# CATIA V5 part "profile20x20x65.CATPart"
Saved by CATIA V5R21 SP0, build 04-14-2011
Part number: 65
Bounding box of the stored display mesh (mm): x -24.289 to -4.289, y -1.335 to 18.665, z 0 to 65
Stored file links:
  C:\Users\2027.DESARCY-LEMIE30\Desktop\V14(17.02.2023)\profile20x20x65.CATPart
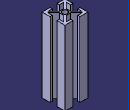
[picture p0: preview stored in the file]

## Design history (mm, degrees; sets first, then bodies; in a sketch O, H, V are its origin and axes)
Body1 (main body)
  Sketch1 on xy-plane, origin (0, 0, 0), H (1, 0, 0), V (0, 1, 0)
    point P1 (-17.2892, 11.6647)
    line L1 (-16.2892, 11.6647) -> (-12.2892, 11.6647)
    point P2 (-11.2892, 11.6647)
    line L2 (-11.2892, 10.6647) -> (-11.2892, 6.6647)
    point P3 (-11.2892, 5.6647)
    line L3 (-12.2892, 5.6647) -> (-16.2892, 5.6647)
    point P4 (-17.2892, 5.6647)
    line L4 (-17.2892, 6.6647) -> (-17.2892, 10.6647)
    point P5 (-24.2892, 18.6647)
    point P6 (-4.2892, 18.6647)
    point P7 (-4.2892, -1.3353)
    line L5 (-11.1892, 18.6647) -> (-11.1892, 16.6647)
    point P8 (-11.1892, 18.6647)
    point P10 (-11.1892, 18.6647)
    point P11 (-17.3892, 18.6647)
    line L6 (-17.3892, 18.6647) -> (-17.3892, 16.6647)
    point P12 (-17.3892, 18.6647)
    line L7 (-11.1892, 18.6647) -> (-4.2892, 18.6647)
    point P14 (-11.1892, 18.6647)
    point P15 (-4.2892, 18.6647)
    point P16 (-11.1892, -1.3353)
    point P17 (-17.3892, -1.3353)
    line L8 (-17.3892, -1.3353) -> (-17.3892, 0.6647)
    point P18 (-17.3892, -1.3353)
    line L9 (-11.1892, -1.3353) -> (-11.1892, 0.6647)
    point P20 (-11.1892, -1.3353)
    line L10 (-24.2892, -1.3353) -> (-17.3892, -1.3353)
    point P22 (-24.2892, -1.3353)
    point P23 (-17.3892, -1.3353)
    line L11 (-11.1892, -1.3353) -> (-4.2892, -1.3353)
    point P24 (-11.1892, -1.3353)
    point P25 (-4.2892, -1.3353)
    line L12 (-24.2892, 18.6647) -> (-17.3892, 18.6647)
    point P26 (-24.2892, 18.6647)
    point P27 (-17.3892, 18.6647)
    point P28 (-4.2892, 5.5647)
    point P29 (-4.2892, 11.7647)
    line L13 (-6.2892, 11.7647) -> (-4.2892, 11.7647)
    point P31 (-4.2892, 11.7647)
    line L14 (-4.2892, 5.5647) -> (-6.2892, 5.5647)
    point P32 (-4.2892, 5.5647)
    point P34 (-24.2892, 5.5647)
    point P35 (-24.2892, 11.7647)
    line L15 (-24.2892, 11.7647) -> (-22.2892, 11.7647)
    point P36 (-24.2892, 11.7647)
    line L16 (-24.2892, 5.5647) -> (-22.2892, 5.5647)
    point P38 (-24.2892, 5.5647)
    line L17 (-4.2892, 18.6647) -> (-4.2892, 11.7647)
    point P40 (-4.2892, 18.6647)
    point P41 (-4.2892, 11.7647)
    line L18 (-24.2892, 18.6647) -> (-24.2892, 11.7647)
    point P42 (-24.2892, 18.6647)
    point P43 (-24.2892, 11.7647)
    line L19 (-24.2892, -1.3353) -> (-24.2892, 5.5647)
    point P44 (-24.2892, -1.3353)
    point P45 (-24.2892, 5.5647)
    line L20 (-4.2892, -1.3353) -> (-4.2892, 5.5647)
    point P46 (-4.2892, -1.3353)
    point P47 (-4.2892, 5.5647)
    line L21 (-22.2892, 5.5647) -> (-22.2892, 1.6647)
    line L22 (-21.2892, 0.6647) -> (-17.3892, 0.6647)
    line L23 (-6.2892, 5.5647) -> (-6.2892, 1.6647)
    line L24 (-11.1892, 0.6647) -> (-7.2892, 0.6647)
    line L25 (-11.1892, 16.6647) -> (-7.2892, 16.6647)
    line L26 (-6.2892, 15.6647) -> (-6.2892, 11.7647)
    line L27 (-17.3892, 16.6647) -> (-21.2892, 16.6647)
    line L28 (-22.2892, 15.6647) -> (-22.2892, 11.7647)
    point P48 (-16.2892, 11.6647)
    point P49 (-17.2892, 10.6647)
    point P50 (-17.2892, 6.6647)
    point P52 (-11.2892, 6.6647)
    point P53 (-11.2892, 10.6647)
    point P54 (-12.2892, 11.6647)
    point P55 (-12.2892, 5.6647)
    line L29 (-16.2892, 11.6647) -> (-21.2892, 16.6647)
    line L30 (-17.2892, 10.6647) -> (-22.2892, 15.6647)
    line L31 (-12.2892, 11.6647) -> (-7.2892, 16.6647)
    line L32 (-16.2892, 5.6647) -> (-21.2892, 0.6647)
    line L33 (-17.2892, 6.6647) -> (-22.2892, 1.6647)
    line L34 (-12.2892, 5.6647) -> (-7.2892, 0.6647)
    line L35 (-11.2892, 6.6647) -> (-6.2892, 1.6647)
    line L36 (-11.2892, 10.6647) -> (-6.2892, 15.6647)
    length L5 = 2
    distance P10 P6 = 6.9
    length L6 = 2
    length L8 = 2
    length L9 = 2
    distance P7 P28 = 6.9
    distance P6 P29 = 6.9
    length L13 = 2
    length L14 = 2
    length L15 = 2
    distance P5 P42 = 0
    length L11 = 6.9
    distance P46 P7 = 0
    distance P1 P48 = 1
    distance P49 P1 = 1
    distance P4 P50 = 1
    distance P54 P2 = 1
    distance P2 P3 = 6
    distance P1 P2 = 6
    horizontal: L1 H, L3 H, L7 H, L10 H, L11 H, L12 H, L13 H, L14 H, L15 H, L16 H, L22 H, L24 H, L25 H, L27 H
    vertical: L2 V, L4 V, L5 V, L6 V, L8 V, L9 V, L17 V, L18 V, L19 V, L20 V, L21 V, L23 V, L26 V, L28 V
    coincidence: P10 P8, P11 P12, P6 P15, P8 P14, P16 L5, P17 L6, P17 P18, P16 P20, P23 L8, P24 L9, P20 P24, P27 L6, P5 P26, P29 P31, P28 P32, P34 L14, P35 L13, P34 P38, P35 P36, P40 L7, P41 L13, P6 P40, P42 L7, P43 L13, P44 L11, P45 L14, P38 P45, P46 L11, P47 L14, P49 L4, P50 L4, P52 L2, P53 L2, P55 L3, P22 P44, P25 P46
    fix: P34, P12, P5, P36, P55
  Pad1: profile Sketch1, direction (0, 0, 1), length 65
  Sketch2 on end face of Pad1, origin (0, 0, 65), H (1, 0, 0), V (0, 1, 0)
    circle A1 centre (-14.2892, 8.6647) radius 2.5
    point P1 (-14.2892, 8.6647)
    reference projected line E1 (-12.2892, 11.6647) -> (-16.2892, 11.6647) from edge [face of Pad1 from Sketch1.L1 | end face of Pad1]
    reference projected line E2 (-11.2892, 6.6647) -> (-11.2892, 10.6647) from edge [face of Pad1 from Sketch1.L2 | end face of Pad1]
    radius A1 = 2.5
    distance P1 E1 = 3
    distance P1 E2 = 3
  Pocket1: profile Sketch2, direction (0, 0, -1), length 105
